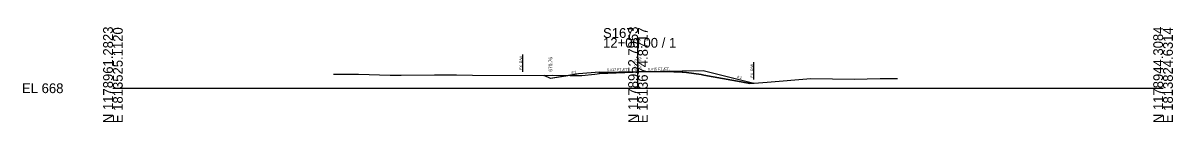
# Model space of a CAD drawing. Extents: x -26 to 6803, y -10 to 1023.
# Drawn here: x -25.7 to 302.8, y 990.3 to 1017.6 of the extents above; entities that cross this region are included whole.
import ezdxf

# ---------------------------------------------------------------- set-up
doc = ezdxf.new("R2010")
doc.units = 0
for name, color, linetype in [('Default', 7, 'Continuous'), ('RD_EX_RW', 7, 'Continuous'), ('RD_GPK_XS_Cell', 7, 'Continuous'), ('RD_XS_EarthShd', 7, 'Continuous'), ('RD_XS_ExGround', 7, 'Continuous'), ('RD_XS_Misc_Line', 7, 'Continuous'), ('RD_XS_Pave', 7, 'Continuous'), ('RD_XS_TieSlope', 7, 'Continuous'), ('RD_XS_TX_Elev_EX', 7, 'Continuous'), ('RD_XS_TX_Elev_PR', 7, 'Continuous'), ('RD_XS_TX_Slope', 7, 'Continuous')]:
    doc.layers.add(name, color=color, linetype=linetype)

msp = doc.modelspace()

# ---------------------------------------------------------------- linework, layer by layer
at = {"layer": 'Default'}
for p, q in [((139.04, 1004.6), (150, 1004.79)), ((150, 1004.79), (162.64, 1004.98))]:
    msp.add_line(p, q, dxfattribs=at)
at = {"layer": 'RD_EX_RW'}
for p, q in [((117, 1009.7), (117, 1004.7)), ((183, 1007.48), (183, 1002.48))]:
    msp.add_line(p, q, dxfattribs=at)
at = {"layer": 'RD_GPK_XS_Cell'}
for p, q in [((150, 1000), (150, 1014.43)), ((0, 1000), (150, 1000)), ((150, 1000), (300, 1000))]:
    msp.add_line(p, q, dxfattribs=at)
at = {"layer": 'RD_XS_EarthShd'}
for p, q in [((139.04, 1004.6), (133.04, 1004.1)), ((162.64, 1004.98), (168.64, 1005.07))]:
    msp.add_line(p, q, dxfattribs=at)
at = {"layer": 'RD_XS_ExGround'}
msp.add_lwpolyline([(63.05, 1004.07), (70.12, 1004.02), (79.23, 1003.78), (82.37, 1003.76), (91.89, 1003.87), (98.12, 1003.83), (102.69, 1003.79), (123.12, 1003.66), (125.57, 1003.8), (133.91, 1003.63), (137.66, 1004.06), (139.04, 1004.21), (148.6, 1004.66), (150, 1004.73), (151.63, 1004.81), (160.21, 1004.67), (162.64, 1004.63), (163.89, 1004.51), (168.01, 1003.9), (168.77, 1003.75), (179.44, 1001.85), (181.91, 1001.36), (186.88, 1001.74), (199.38, 1002.76), (211.79, 1002.6), (219.19, 1002.78), (221.21, 1002.76), (224.14, 1002.8)], dxfattribs=at)
at = {"layer": 'RD_XS_Misc_Line'}
for points in [[(125, 1002.76), (123.19, 1003.67), (125.57, 1003.8), (130.62, 1003.7)], [(125, 1002.76), (123.19, 1003.67), (125.57, 1003.8), (130.62, 1003.7)], [(125, 1002.76), (123.19, 1003.67), (125.57, 1003.8), (130.62, 1003.7)], [(125.57, 1003.8), (130.62, 1003.7), (125, 1002.76), (123.19, 1003.67)], [(125.57, 1003.8), (130.62, 1003.7), (125, 1002.76), (123.19, 1003.67)], [(139.04, 1004.21), (139.04, 1004.6), (133.04, 1004.1), (130.62, 1003.7), (133.91, 1003.63), (137.66, 1004.06)], [(139.04, 1004.21), (139.04, 1004.6), (133.04, 1004.1), (130.62, 1003.7), (133.91, 1003.63), (137.66, 1004.06)], [(139.04, 1004.21), (139.04, 1004.6), (133.04, 1004.1), (130.62, 1003.7), (133.91, 1003.63), (137.66, 1004.06)], [(130.62, 1003.7), (133.91, 1003.63), (137.66, 1004.06), (139.04, 1004.21), (139.04, 1004.6), (133.04, 1004.1)], [(130.62, 1003.7), (133.91, 1003.63), (137.66, 1004.06), (139.04, 1004.21), (139.04, 1004.6), (133.04, 1004.1)], [(139.04, 1004.21), (139.04, 1004.6), (150, 1004.79), (162.64, 1004.98), (162.64, 1004.63), (160.21, 1004.67), (151.63, 1004.81), (150, 1004.73), (148.6, 1004.66)], [(139.04, 1004.21), (139.04, 1004.6), (150, 1004.79), (162.64, 1004.98), (162.64, 1004.63), (160.21, 1004.67), (151.63, 1004.81), (150, 1004.73), (148.6, 1004.66)], [(139.04, 1004.21), (139.04, 1004.6), (150, 1004.79), (162.64, 1004.98), (162.64, 1004.63), (160.21, 1004.67), (151.63, 1004.81), (150, 1004.73), (148.6, 1004.66)], [(150, 1004.79), (162.64, 1004.98), (162.64, 1004.63), (160.21, 1004.67), (151.63, 1004.81), (150, 1004.73), (148.6, 1004.66), (139.04, 1004.21), (139.04, 1004.6)], [(150, 1004.79), (162.64, 1004.98), (162.64, 1004.63), (160.21, 1004.67), (151.63, 1004.81), (150, 1004.73), (148.6, 1004.66), (139.04, 1004.21), (139.04, 1004.6)], [(162.64, 1004.98), (168.64, 1005.07), (183.1, 1001.45), (181.91, 1001.36), (179.44, 1001.85), (168.77, 1003.75), (168.01, 1003.9), (163.89, 1004.51), (162.64, 1004.63)], [(162.64, 1004.98), (168.64, 1005.07), (183.1, 1001.45), (181.91, 1001.36), (179.44, 1001.85), (168.77, 1003.75), (168.01, 1003.9), (163.89, 1004.51), (162.64, 1004.63)], [(162.64, 1004.98), (168.64, 1005.07), (183.1, 1001.45), (181.91, 1001.36), (179.44, 1001.85), (168.77, 1003.75), (168.01, 1003.9), (163.89, 1004.51), (162.64, 1004.63)], [(168.64, 1005.07), (183.1, 1001.45), (181.91, 1001.36), (179.44, 1001.85), (168.77, 1003.75), (168.01, 1003.9), (163.89, 1004.51), (162.64, 1004.63), (162.64, 1004.98)], [(168.64, 1005.07), (183.1, 1001.45), (181.91, 1001.36), (179.44, 1001.85), (168.77, 1003.75), (168.01, 1003.9), (163.89, 1004.51), (162.64, 1004.63), (162.64, 1004.98)]]:
    msp.add_lwpolyline(points, close=True, dxfattribs=at)
at = {"layer": 'RD_XS_Pave'}
for p, q in [((139.04, 1004.21), (139.04, 1004.6)), ((162.64, 1004.98), (162.64, 1004.63))]:
    msp.add_line(p, q, dxfattribs=at)
at = {"layer": 'RD_XS_TieSlope'}
for p, q in [((125, 1002.76), (123.2, 1003.66)), ((133.04, 1004.1), (125, 1002.76)), ((168.64, 1005.07), (183.1, 1001.45))]:
    msp.add_line(p, q, dxfattribs=at)

# ---------------------------------------------------------------- texts
at = {"layer": 'RD_EX_RW'}
for p in [(116.94, 1005.23), (182.94, 1003)]:
    msp.add_text('EX. R/W', height=0.75, rotation=90, dxfattribs=at).set_placement(p)
at = {"layer": 'RD_GPK_XS_Cell'}
for s, p in [('N 1178961.2823', (0, 990)), ('E 1813525.1120', (2.8, 990)), ('N 1178952.7953', (150, 990)), ('E 1813674.8717', (152.8, 990)), ('N 1178944.3084', (300, 990)), ('E 1813824.6314', (302.8, 990))]:
    msp.add_text(s, height=2.8, rotation=90, dxfattribs=at).set_placement(p)
for s, p in [('S167', (140, 1014.43)), ('12+00.00 / 1', (140, 1011.63)), ('EL 668', (-26, 998.6))]:
    msp.add_text(s, height=2.8, dxfattribs=at).set_placement(p)
at = {"layer": 'RD_XS_TX_Elev_EX'}
msp.add_text('672.73', height=0.8, rotation=90, dxfattribs=at).set_placement((149.86, 1005))
at = {"layer": 'RD_XS_TX_Elev_PR'}
for s, height, p in [('670.76', 1, (125.5, 1004.76)), ('672.79', 0.8, (150.93, 1005.46))]:
    msp.add_text(s, height=height, rotation=90, dxfattribs=at).set_placement(p)
at = {"layer": 'RD_XS_TX_Slope'}
for s, rotation, p in [('0.017 FT./FT.', 0.9888, (141.15, 1004.89)), ('0.015 FT./FT.', 0.8484, (152.86, 1005.08)), ('6:1', 14.0362, (131.06, 1004)), ('4:1', 345.9638, (178.19, 1002.94))]:
    msp.add_text(s, height=0.75, rotation=rotation, dxfattribs=at).set_placement(p)

doc.saveas('drawing.dxf')
